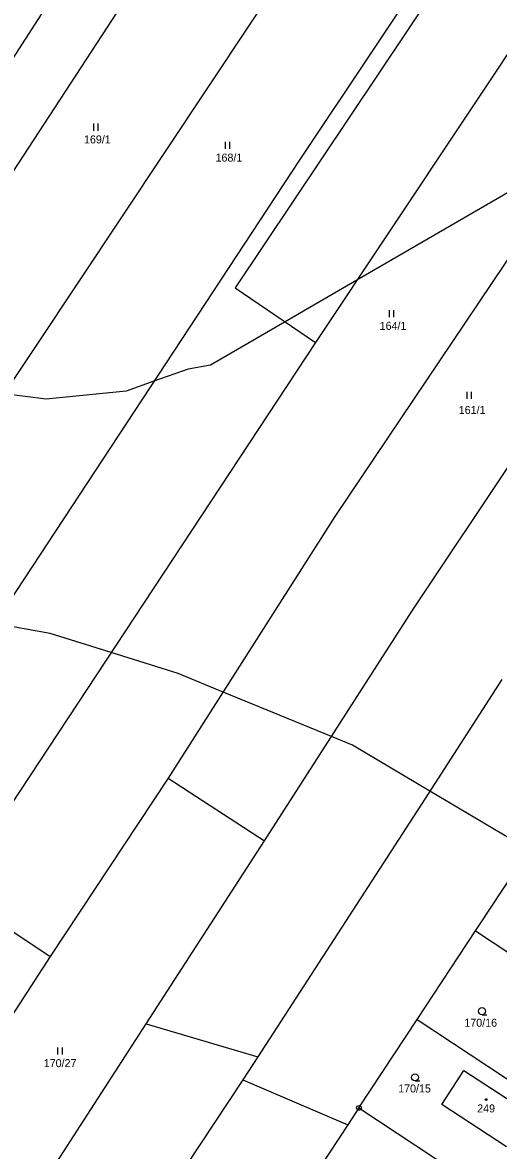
# Model space of a CAD drawing. Extents: x -747333 to -745433, y -1133152 to -1130600.
# Drawn here: x -746635.6 to -746534.4, y -1131861.6 to -1131622 of the extents above; entities that cross this region are included whole.
import ezdxf

# ---------------------------------------------------------------- set-up
doc = ezdxf.new("R2010")
doc.units = 0
for name, color, linetype in [('Vrstva 1', 7, 'Continuous'), ('Vrstva 18', 7, 'Continuous'), ('Vrstva 19', 7, 'Continuous'), ('Vrstva 24', 7, 'Continuous'), ('Vrstva 25', 7, 'Continuous'), ('Vrstva 3', 7, 'Continuous'), ('Vrstva 37', 7, 'Continuous'), ('Vrstva 52', 7, 'Continuous'), ('Vrstva 6', 7, 'Continuous')]:
    doc.layers.add(name, color=color, linetype=linetype)

msp = doc.modelspace()

# ---------------------------------------------------------------- linework, layer by layer
at = {"layer": 'Vrstva 1'}
for p, q in [((-746546.42, -1131851.79), (-746541.73, -1131844.57)), ((-746541.73, -1131844.57), (-746527.94, -1131853.59)), ((-746532.65, -1131860.81), (-746546.42, -1131851.79))]:
    msp.add_line(p, q, dxfattribs=at)
for points in [[(-746538.26, -1131813.41), (-746526.88, -1131796.16)], [(-746539.27, -1131814.94), (-746538.26, -1131813.41)], [(-746551.66, -1131833.72), (-746539.27, -1131814.94)], [(-746539.27, -1131814.94), (-746509.21, -1131834.76)], [(-746564.05, -1131852.51), (-746551.66, -1131833.72)], [(-746551.66, -1131833.72), (-746521.6, -1131853.55)], [(-746564.05, -1131852.51), (-746566.41, -1131856.09)], [(-746564.05, -1131852.51), (-746543.81, -1131865.86)], [(-746566.41, -1131856.09), (-746576.43, -1131871.29)]]:
    msp.add_lwpolyline(points, dxfattribs=at)
at = {"layer": 'Vrstva 24'}
msp.add_line((-746564.1, -1131852.51), (-746564, -1131852.51), dxfattribs=at)
msp.add_circle((-746564.05, -1131852.51), 0.499289, dxfattribs=at)
at = {"layer": 'Vrstva 25'}
for p, q in [((-746620.47, -1131643.46), (-746620.47, -1131644.96)), ((-746619.47, -1131644.96), (-746619.47, -1131643.46)), ((-746592.48, -1131647.33), (-746592.48, -1131648.83)), ((-746591.48, -1131648.83), (-746591.48, -1131647.33)), ((-746557.62, -1131683.06), (-746557.62, -1131684.56)), ((-746556.62, -1131684.56), (-746556.62, -1131683.06)), ((-746541.09, -1131700.43), (-746541.09, -1131701.93)), ((-746540.09, -1131701.93), (-746540.09, -1131700.43)), ((-746537.88, -1131832.72), (-746536.88, -1131832.72)), ((-746628.09, -1131839.66), (-746628.09, -1131841.16)), ((-746627.09, -1131841.16), (-746627.09, -1131839.66)), ((-746552.12, -1131846.79), (-746551.12, -1131846.79))]:
    msp.add_line(p, q, dxfattribs=at)
for centre, radius in [((-746537.88, -1131831.97), 0.75), ((-746552.12, -1131846.04), 0.75), ((-746537.01, -1131850.75), 0.174503)]:
    msp.add_circle(centre, radius, dxfattribs=at)
at = {"layer": 'Vrstva 3'}
for points in [[(-746546.42, -1131851.79), (-746541.73, -1131844.57)], [(-746541.73, -1131844.57), (-746527.94, -1131853.59)], [(-746532.65, -1131860.81), (-746546.42, -1131851.79)]]:
    msp.add_lwpolyline(points, dxfattribs=at)
at = {"layer": 'Vrstva 37'}
msp.add_circle((-746537.01, -1131850.75), 0.174503, dxfattribs=at)
at = {"layer": 'Vrstva 52'}
for points in [[(-746371.94, -1131696.87), (-746376.19, -1131692.62), (-746393.19, -1131675.2), (-746393.62, -1131674.75), (-746399.87, -1131669.31), (-746417, -1131654.38), (-746428.32, -1131646.71), (-746436.56, -1131641.13), (-746449.75, -1131637.75), (-746450.6, -1131637.66), (-746466.81, -1131636), (-746479.61, -1131637.14), (-746486.37, -1131637.75), (-746503.37, -1131642.87), (-746509.75, -1131645), (-746516.81, -1131649.09), (-746564.47, -1131676.7), (-746579.73, -1131685.54), (-746595.62, -1131694.75), (-746600.31, -1131695.62), (-746607.62, -1131698.19), (-746613.5, -1131700.25), (-746630.5, -1131702), (-746639.49, -1131700.88)], [(-746527.9, -1131797.71), (-746548.99, -1131785.24), (-746565.44, -1131775.5), (-746569.9, -1131773.66), (-746592.89, -1131764.19), (-746602.44, -1131760.25), (-746616.73, -1131755.79), (-746629.69, -1131751.75), (-746641.55, -1131749.64), (-746668.73, -1131744.82), (-746672.62, -1131744.12), (-746692.56, -1131737.63), (-746700.25, -1131735.13), (-746703.89, -1131732.48), (-746706.63, -1131730.5), (-746713.92, -1131725.64), (-746719.38, -1131722), (-746732.41, -1131712.01), (-746741.06, -1131705.38)]]:
    msp.add_lwpolyline(points, dxfattribs=at)
at = {"layer": 'Vrstva 6'}
for points in [[(-746664.87, -1131671.92), (-746597.56, -1131567.52)], [(-746589.72, -1131580.27), (-746695.71, -1131742.45)], [(-746545.3, -1131604.15), (-746576.72, -1131651.31)], [(-746541.73, -1131605.72), (-746590.37, -1131678.32)], [(-746669.36, -1131745.76), (-746577.87, -1131608.3)], [(-746525.57, -1131618.34), (-746573.28, -1131689.92)], [(-746510.85, -1131640.22), (-746569.14, -1131726.93)], [(-746576.72, -1131651.31), (-746648.61, -1131760.36)], [(-746590.37, -1131678.32), (-746573.28, -1131689.92)], [(-746573.28, -1131689.92), (-746650.27, -1131806.65)], [(-746552.72, -1131746.93), (-746530.72, -1131713.92)], [(-746569.14, -1131726.93), (-746604.57, -1131782.51)], [(-746584.14, -1131795.8), (-746552.72, -1131746.93)], [(-746533.7, -1131761.53), (-746550, -1131786.81)], [(-746604.57, -1131782.51), (-746629.7, -1131820.37)], [(-746604.57, -1131782.51), (-746584.14, -1131795.8)], [(-746550, -1131786.81), (-746585.55, -1131841.66)], [(-746609.27, -1131834.66), (-746584.14, -1131795.8)], [(-746650.27, -1131806.65), (-746629.7, -1131820.37)], [(-746629.7, -1131820.37), (-746668.22, -1131879.72)], [(-746631.27, -1131868.67), (-746609.27, -1131834.66)], [(-746609.27, -1131834.66), (-746585.55, -1131841.66)], [(-746585.55, -1131841.66), (-746588.71, -1131846.53)], [(-746588.71, -1131846.53), (-746631.67, -1131911.42)], [(-746588.71, -1131846.53), (-746566.41, -1131856.09)]]:
    msp.add_lwpolyline(points, dxfattribs=at)

# ---------------------------------------------------------------- texts
at = {"layer": 'Vrstva 18'}
for s, p in [('169/1', (-746622.49, -1131647.66)), ('168/1', (-746594.52, -1131651.53)), ('164/1', (-746559.64, -1131687.26)), ('161/1', (-746542.83, -1131705.13)), ('170/16', (-746541.63684, -1131835.28)), ('170/27', (-746631.04, -1131843.86)), ('170/15', (-746555.705458, -1131849.24))]:
    msp.add_text(s, height=1.7, dxfattribs=at).set_placement(p)
at = {"layer": 'Vrstva 19'}
msp.add_text('249', height=1.7, dxfattribs=at).set_placement((-746538.907496, -1131853.48))

doc.saveas('drawing.dxf')
